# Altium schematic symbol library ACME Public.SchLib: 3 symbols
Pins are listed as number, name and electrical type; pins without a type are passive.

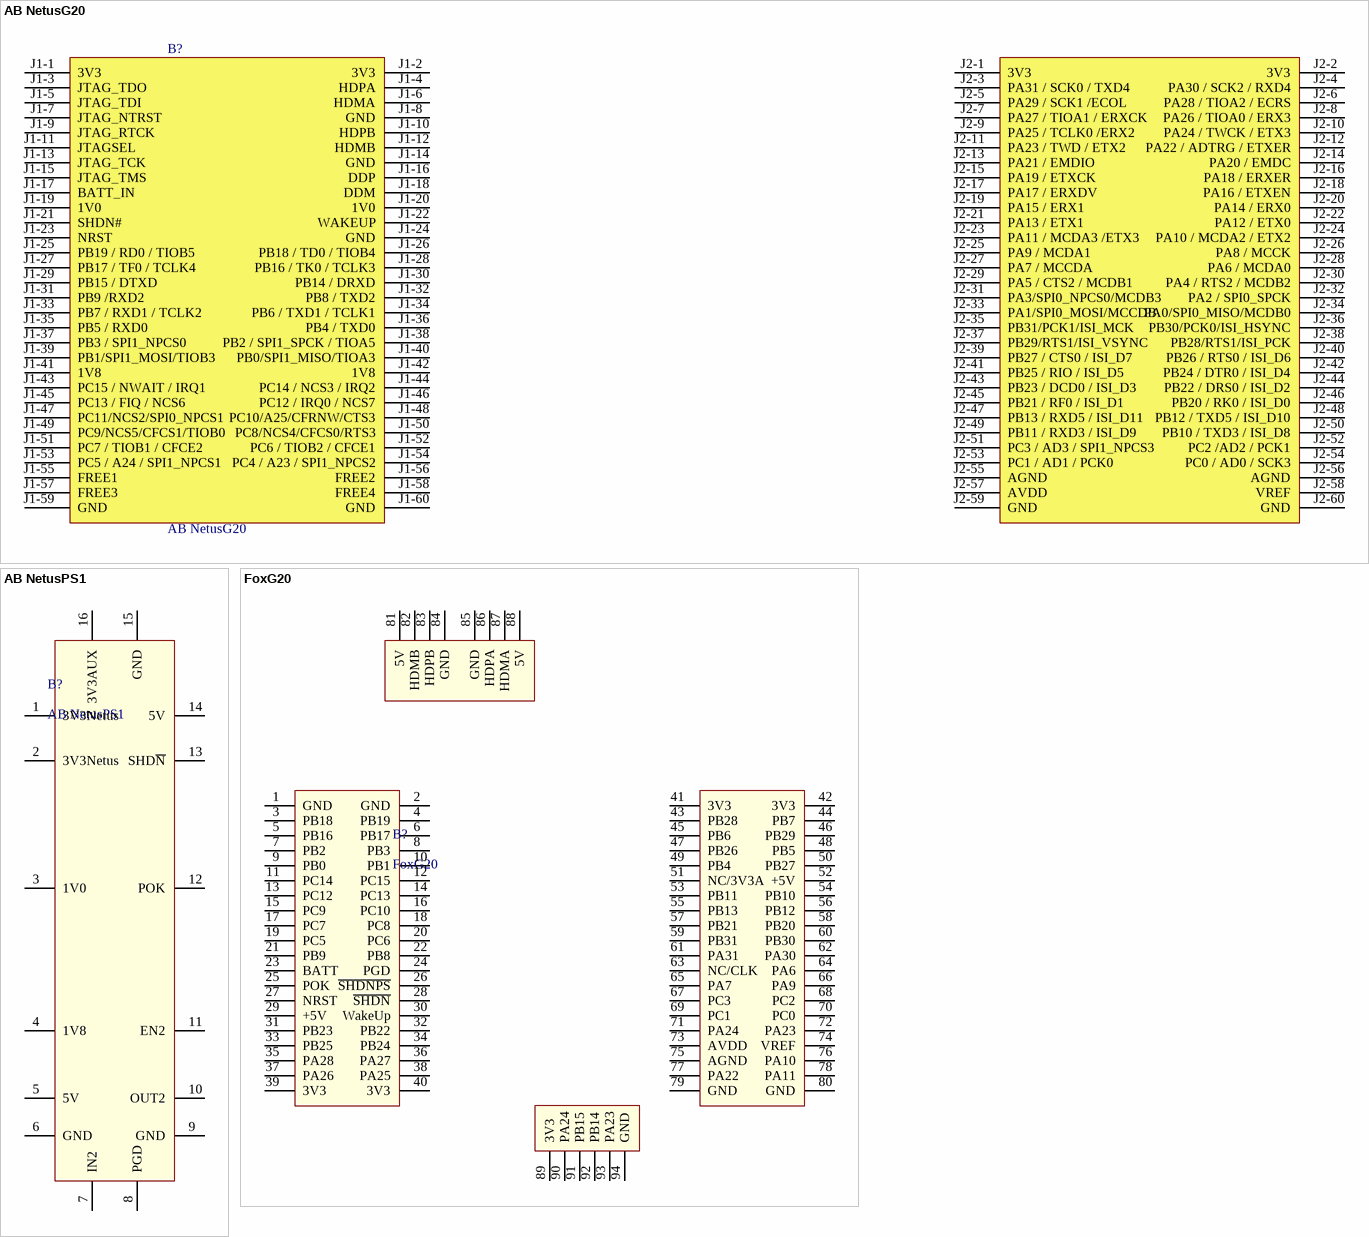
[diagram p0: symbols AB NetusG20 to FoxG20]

## AB NetusG20
designator B?
NetusG20
footprint NetusDaughter1 (PAD for Netus_Core_1 Board to be used in daughter boards)
pins: J1-1 3V3   , J1-2    3V3, J1-3 JTAG_TDO, J1-4 HDPA, J1-5 JTAG_TDI, J1-6 HDMA, J1-7 JTAG_NTRST, J1-8    GND, J1-9 JTAG_RTCK, J1-10 HDPB, J1-11 JTAGSEL, J1-12 HDMB, J1-13 JTAG_TCK, J1-14    GND, J1-15 JTAG_TMS, J1-16 DDP, J1-17 BATT_IN, J1-18 DDM, J1-19 1V0, J1-20    1V0, J1-21 SHDN#, J1-22 WAKEUP, J1-23 NRST, J1-24    GND, J1-25 PB19 / RD0 / TIOB5, J1-26 PB18 / TD0 / TIOB4, J1-27 PB17 / TF0 / TCLK4, J1-28 PB16 / TK0 / TCLK3, J1-29 PB15 / DTXD, J1-30 PB14 / DRXD, J1-31 PB9 /RXD2, J1-32 PB8 / TXD2, J1-33 PB7 / RXD1 / TCLK2, J1-34 PB6 / TXD1 / TCLK1, J1-35 PB5 / RXD0, J1-36 PB4 / TXD0, J1-37 PB3 / SPI1_NPCS0, J1-38 PB2 / SPI1_SPCK / TIOA5, J1-39 PB1/SPI1_MOSI/TIOB3, J1-40 PB0/SPI1_MISO/TIOA3, J1-41 1V8, J1-42    1V8, J1-43 PC15 / NWAIT / IRQ1, J1-44 PC14 / NCS3 / IRQ2, J1-45 PC13 / FIQ / NCS6, J1-46 PC12 / IRQ0 / NCS7, J1-47 PC11/NCS2/SPI0_NPCS1, J1-48 PC10/A25/CFRNW/CTS3, J1-49 PC9/NCS5/CFCS1/TIOB0, J1-50 PC8/NCS4/CFCS0/RTS3, J1-51 PC7 / TIOB1 / CFCE2, J1-52 PC6 / TIOB2 / CFCE1, J1-53 PC5 / A24 / SPI1_NPCS1, J1-54 PC4 / A23 / SPI1_NPCS2, J1-55 FREE1, J1-56 FREE2, J1-57 FREE3, J1-58 FREE4, J1-59 GND   , J1-60    GND, J2-1 3V3   , J2-2    3V3, J2-3 PA31 / SCK0 / TXD4, J2-4 PA30 / SCK2 / RXD4, J2-5 PA29 / SCK1 /ECOL, J2-6 PA28 / TIOA2 / ECRS, J2-7 PA27 / TIOA1 / ERXCK, J2-8 PA26 / TIOA0 / ERX3, J2-9 PA25 / TCLK0 /ERX2, J2-10 PA24 / TWCK / ETX3, J2-11 PA23 / TWD / ETX2, J2-12 PA22 / ADTRG / ETXER, J2-13 PA21 / EMDIO, J2-14 PA20 / EMDC, J2-15 PA19 / ETXCK, J2-16 PA18 / ERXER, J2-17 PA17 / ERXDV, J2-18 PA16 / ETXEN, J2-19 PA15 / ERX1, J2-20 PA14 / ERX0, J2-21 PA13 / ETX1, J2-22 PA12 / ETX0, J2-23 PA11 / MCDA3 /ETX3, J2-24 PA10 / MCDA2 / ETX2, J2-25 PA9 / MCDA1, J2-26 PA8 / MCCK, J2-27 PA7 / MCCDA, J2-28 PA6 / MCDA0, J2-29 PA5 / CTS2 / MCDB1, J2-30 PA4 / RTS2 / MCDB2, J2-31 PA3/SPI0_NPCS0/MCDB3, J2-32 PA2 / SPI0_SPCK, J2-33 PA1/SPI0_MOSI/MCCDB, J2-34 PA0/SPI0_MISO/MCDB0, J2-35 PB31/PCK1/ISI_MCK, J2-36 PB30/PCK0/ISI_HSYNC, J2-37 PB29/RTS1/ISI_VSYNC, J2-38 PB28/RTS1/ISI_PCK, J2-39 PB27 / CTS0 / ISI_D7, J2-40 PB26 / RTS0 / ISI_D6, J2-41 PB25 / RIO / ISI_D5, J2-42 PB24 / DTR0 / ISI_D4, J2-43 PB23 / DCD0 / ISI_D3, J2-44 PB22 / DRS0 / ISI_D2, J2-45 PB21 / RF0 / ISI_D1, J2-46 PB20 / RK0 / ISI_D0, J2-47 PB13 / RXD5 / ISI_D11, J2-48 PB12 / TXD5 / ISI_D10, J2-49 PB11 / RXD3 / ISI_D9, J2-50 PB10 / TXD3 / ISI_D8, J2-51 PC3 / AD3 / SPI1_NPCS3, J2-52 PC2 /AD2 / PCK1, J2-53 PC1 / AD1 / PCK0, J2-54 PC0 / AD0 / SCK3, J2-55 AGND, J2-56 AGND, J2-57 AVDD, J2-58 VREF, J2-59 GND   , J2-60    GND

## AB NetusPS1
designator B?
PS1 Quad Power Supply
footprint NETUSPS1
pins: 1 3V3Netus, 2 3V3Netus, 3 1V0, 4 1V8, 5 5V, 6 GND, 7 IN2, 8 PGD, 9 GND, 10 OUT2, 11 EN2, 12 POK, 13 SHD~{N}, 14 5V, 15 GND, 16 3V3AUX

## FoxG20
designator B?
Fox Board G20 standard
footprint FoxG20 (Connector; Header; 20x2 Position)
pins: 1 GND, 2 GND, 3 PB18, 4 PB19, 5 PB16, 6 PB17, 7 PB2, 8 PB3, 9 PB0, 10 PB1, 11 PC14, 12 PC15, 13 PC12, 14 PC13, 15 PC9, 16 PC10, 17 PC7, 18 PC8, 19 PC5, 20 PC6, 21 PB9, 22 PB8, 23 BATT, 24 PGD, 25 POK, 26 ~{SHDNPS}, 27 NRST, 28 ~{SHDN}, 29 +5V, 30 WakeUp, 31 PB23, 32 PB22, 33 PB25, 34 PB24, 35 PA28, 36 PA27, 37 PA26, 38 PA25, 39 3V3, 40 3V3, 41 3V3, 42 3V3, 43 PB28, 44 PB7, 45 PB6, 46 PB29, 47 PB26, 48 PB5, 49 PB4, 50 PB27, 51 NC/3V3A, 52 +5V, 53 PB11, 54 PB10, 55 PB13, 56 PB12, 57 PB21, 58 PB20, 59 PB31, 60 PB30, 61 PA31, 62 PA30, 63 NC/CLK, 64 PA6, 65 PA7, 66 PA9, 67 PC3, 68 PC2, 69 PC1, 70 PC0, 71 PA24, 72 PA23, 73 AVDD, 74 VREF, 75 AGND, 76 PA10, 77 PA22, 78 PA11, 79 GND, 80 GND, 81 5V, 82 HDMB, 83 HDPB, 84 GND, 85 GND, 86 HDPA, 87 HDMA, 88 5V, 89 3V3, 90 PA24, 91 PB15, 92 PB14, 93 PA23, 94 GND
